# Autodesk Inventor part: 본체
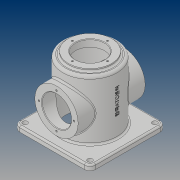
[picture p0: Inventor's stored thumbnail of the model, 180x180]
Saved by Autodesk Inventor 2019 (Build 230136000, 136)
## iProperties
Created: 2019-03
Part Number: 본체
Material: 일반
Document SubType Name: Modeling
Designer: PC312-08
Density: 1 g/cm^3
Appearance: 기본값
Author: PC312-08
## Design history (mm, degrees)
sketch "스케치1"
  geometry: C1 r 50 at (0, 0); 1 further point
  constraints: 1 centre point, 1 coincident
  dimensions: "d0" = 100 diameter of C1
extrude "돌출1" new body sketch "스케치1" stored distance "d1" = 110; taper "d2" = 0 deg
sketch "스케치2"
  geometry: L1 (-70, -70)-(70, -70); L2 (70, -70)-(70, 70); L3 (70, 70)-(-70, 70); L4 (-70, 70)-(-70, -70); L5 (-70, -70)-(70, 70); L6 (70, -70)-(-70, 70); 1 further point
  constraints: 12 end point, 2 midpoint, 2 parallel, 1 horizontal, 1 perpendicular
  dimensions: "d3" = 140 distance of L3.end L2.end; "d4" = 140 distance of L2.end L1.end
extrude "돌출2" join sketch "스케치2" distance "d5" = 10; taper "d6" = 0 deg
sketch "스케치3"
  geometry: C1 r 40 at (0, 0); 1 further point
  constraints: 1 centre point, 1 coincident
  dimensions: "d7" = 80 diameter of C1
extrude "돌출3" join sketch "스케치3" distance "d8" = 5; taper "d9" = 0 deg
sketch "스케치4"
  geometry: C1 r 45 at (0, 0); 1 further point
  constraints: 1 centre point, 1 coincident
  dimensions: "d10" = 90 diameter of C1
extrude "돌출4" cut sketch "스케치4" distance "d11" = 112; taper "d12" = 0 deg
sketch "스케치5"
  geometry: C1 r 27 at (0, 0); 1 further point
  constraints: 1 centre point, 1 coincident
  dimensions: "d13" = 54 diameter of C1
extrude "돌출5" cut sketch "스케치5" distance "d14" = 13; taper "d15" = 0 deg
node "작업 평면1"
sketch "스케치6"
  geometry: L1 (70, -65)-(-70, -65) reference; C1 r 40 at (0, -5); 1 further point
  constraints: 1 centre point, 1 vertical alignment
  dimensions: "d17" = 80 diameter of C1; "d18" = 60 distance from line of L1 C1.centre
extrude "돌출6" join sketch "스케치6" stored distance "d19" = 13; taper "d20" = 0 deg
sketch "스케치7" dims "d21" = 65
  geometry: L1 (70, -60)-(-70, -60) reference; L2 (0, 0)-(0, 32.5); 2 further points
  constraints: 2 end point, 2 vertical alignment, 1 coincident, 1 vertical, 2 other
  dimensions: "d22" = 60 distance from line of L1 L2.start
hole "구멍1" sketch "스케치7" at (0, 32.5) diameter "d23" = 3.242; stored, may be unused: countersink angle "d27" = 90 deg, drill point angle "d29" = 118 deg; dims "d24" = 8, "d25" = 4, "d26" = 2, "d28" = 10
sketch "스케치8"
  geometry: L1 (70, -60)-(-70, -60) reference; C1 r 27 at (0, 0); 1 further point
  constraints: 1 centre point, 1 vertical alignment
  dimensions: "d33" = 54 diameter of C1; "d34" = 60 distance from line of L1 C1.centre
extrude "돌출7" cut sketch "스케치8" stored distance "d35" = 13; taper "d36" = 0 deg
sketch "스케치10" dims "d37" = 65
  geometry: L1 (0, 0)-(0, 32.5); 2 further points
  constraints: 2 coincident, 2 end point, 1 vertical, 1 vertical alignment, 2 other
hole "구멍2" sketch "스케치10" at (0, 32.5) diameter "d38" = 3.242; stored, may be unused: countersink angle "d42" = 90 deg, drill point angle "d44" = 118 deg; dims "d39" = 8, "d40" = 4, "d41" = 2, "d43" = 10
fillet "모깎기1" dims "d48" = 10
sketch "스케치11"
  geometry: A1 r 10 centre (-60, -60) between (-70, -60) and (-60, -70) reference; A2 r 10 centre (-60, 60) between (-60, 70) and (-70, 60) reference; A3 r 10 centre (60, 60) between (70, 60) and (60, 70) reference; A4 r 10 centre (60, -60) between (60, -70) and (70, -60) reference; 5 further points
  constraints: 4 coincident
hole "구멍3" sketch "스케치11" at (-60, -60), (-60, 60), (60, 60), (60, -60) diameter "d49" = 9; stored, may be unused: countersink angle "d53" = 90 deg, drill point angle "d55" = 118 deg; dims "d50" = 8, "d51" = 4, "d52" = 2, "d54" = 10
chamfer "모따기1" distance "d56" = 1; stored, may be unused: second distance "d57" = 2, angle "d58" = 45 deg
fillet "모깎기2" dims "d59" = 5
fillet "모깎기3" dims "d60" = 3
fillet "모깎기4" dims "d61" = 3
node "작업 평면2"
sketch "스케치12"
  geometry: L1 (-65, -60)-(-65, 60) reference; 2 further points
  constraints: 1 horizontal alignment, 1 other
  dimensions: "d63" = 70 distance from line of L1 point (5, 0)
feature "엠보싱1" sketch "스케치12" dims "d1" = 110, "d2" = 0, "d64" = 0.5, "d65" = 0
node "솔리드1"
pattern_circular "원형 패턴1" dims angle "d31" = 360 deg
mirror "미러1"
pattern_circular "원형 패턴2" dims angle "d46" = 360 deg
other parameters: "d16" = 62, "d62" = 53.25
